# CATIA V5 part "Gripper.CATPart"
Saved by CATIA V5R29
Part number: Gripper
Bounding box of the stored display mesh (mm): x -95 to 95, y -290 to 38, z -94.974 to 283.5
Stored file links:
  C:\Users\Administrator\Desktop\프로젝트\Gripper\Gripper.CATPart
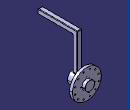
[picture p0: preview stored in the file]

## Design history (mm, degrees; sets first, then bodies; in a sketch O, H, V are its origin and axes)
Body1 (main body)
  Sketch1 on zx-plane, origin (0, 0, 0), H (-1, 0, 0), V (0, 0, 1)
    circle A1 centre (0, 0) radius 95
    radius A1 = 95
  Pad1: profile Sketch1, direction (0, 1, 0), length 18
  Sketch2 on end face of Pad1, origin (0, 18, 0), H (-1, 0, 0), V (0, 0, 1)
    circle A1 centre (0, 40) radius 2.459
    point P1 (0, 40)
    radius A1 = 2.459
    distance P1 H = 40
    coincidence: P1 V
  Pad2: profile Sketch2, direction (0, 1, 0), length 15
  CircPattern1: of Pad2, instances 5, angular step 90, axis from face of Pad1 from Sketch1.A1
  Sketch3 on end face of Pad1, origin (0, 18, 0), H (-1, 0, 0), V (0, 0, 1)
    circle A1 centre (56.5685, 56.5685) radius 5
    point P1 (56.5685, 56.5685)
    construction circle A2 centre (0, 0) radius 80
    construction line L1 (56.5685, 56.5685) -> (0, 0)
    radius A1 = 5
    radius A2 = 80
    angle L1 H = 45
    coincidence: P1 A2
  Pocket1: profile Sketch3, direction (0, -1, 0), through (limit type 6)
  CircPattern2: of Pocket1, instances 2, angular step 180, axis from face of Pad1 from Sketch1.A1
  Sketch4 on end face of Pad1, origin (0, 18, 0), H (-1, 0, 0), V (0, 0, 1)
    circle A1 centre (77.2741, 20.7055) radius 4.188
    construction line L1 (77.2741, 20.7055) -> (0, 0)
    construction line L2 (56.5685, 56.5685) -> (0, 0)
    point P2 (56.5685, 56.5685)
    reference projected point E1 (56.5685, 56.5685) from axis of face of Pocket1 from Sketch3.A1
    radius A1 = 4.188
    angle L2 L1 = 30
    length L1 = 80
    coincidence: P2 E1
  Pocket2: profile Sketch4, direction (0, -1, 0), through (limit type 6)
  CircPattern3: of Pocket2, instances 5, angular step 30, axis from face of Pad1 from Sketch1.A1
  Sketch5 on end face of Pad1, origin (0, 18, 0), H (-1, 0, 0), V (0, 0, 1)
    circle A1 centre (20.7055, 77.2741) radius 4.188
    construction line L1 (20.7055, 77.2741) -> (0, 0)
    construction line L2 (56.5685, 56.5685) -> (0, 0)
    point P2 (56.5685, 56.5685)
    reference projected point E3 (56.5685, 56.5685) from axis of face of Pocket1 from Sketch3.A1
    radius A1 = 4.188
    angle L2 L1 = 30
    length L1 = 80
    coincidence: P2 E3
  Pocket3: profile Sketch5, direction (0, -1, 0), through (limit type 6)
  CircPattern4: of Pocket3, instances 5, angular step 30, axis from face of Pad1 from Sketch1.A1
  Sketch6 on end face of Pad1, origin (0, 18, 0), H (-1, 0, 0), V (0, 0, 1)
    circle A1 centre (0, 0) radius 31.5
    radius A1 = 31.5
  Pad3: profile Sketch6, direction (0, 1, 0), length 20
  Fillet1: radius 1, on end face of Pad3
  Plane1: type Offset, RefPlane zx-plane, Offset 20, reversed
  Sketch7 on yz-plane, origin (0, 0, 0), H (0, 1, 0), V (0, 0, 1)
    line L1 (0, 60) -> (-20, 40)
  Sketch8 on Plane1, origin (0, -20, 0), H (-1, 0, 0), V (0, 0, 1)
    circle A1 centre (0, 0) radius 40
    radius A1 = 40
  Sketch9 on zx-plane, origin (0, 0, 0), H (-1, 0, 0), V (0, 0, 1)
    circle A1 centre (0, 0) radius 60
    radius A1 = 60
  Loft1: solid, Sections (Sketch8; Sketch9), Guides Sketch7
  Sketch10 on face of Loft1, origin (0, -20, 0), H (1, 0, 0), V (0, 0, 1)
    circle A1 centre (0, 0) radius 40
    reference projected circle E1 centre (0, 0) radius 40 from edge [face of Loft1 | face of Loft1]
    coincidence: A1 E1
  Pad4: profile Sketch10, direction (0, -1, 0), length 50
  Sketch11 on xy-plane, origin (0, 0, 0), H (1, 0, 0), V (0, 1, 0)
    point P1 (0, -45)
    line L1 (15, -30) -> (15, -60)
    line L2 (15, -60) -> (-15, -60)
    line L3 (-15, -60) -> (-15, -30)
    line L4 (-15, -30) -> (15, -30)
    reference intersected line E1 through (0, -20) direction (-1, 0) from Plane1
    distance L4 L2 = 30
    distance L1 L3 = 30
    distance L4 E1 = 10
    coincidence: P1 V
    vertical: L1 V, L3 V
    horizontal: L2 H, L4 H
    equidistance: L1 L3 P1, L2 L4 P1
  Pad5: profile Sketch11, direction (0, 0, 1), length 283.5
  Sketch12 on face of Pad5 from Sketch11.L2, origin (0, -60, 0), H (1, 0, 0), V (0, 0, 1)
    line L1 (-15, 283.5) -> (15, 283.5)
    line L2 (15, 283.5) -> (15, 253.5)
    line L3 (15, 253.5) -> (-15, 253.5)
    line L4 (-15, 253.5) -> (-15, 283.5)
    reference projected line E1 (15, 0) -> (15, 283.5) from edge [face of Pad5 from Sketch11.L1 | face of Pad5 from Sketch11.L2]
    reference projected line E2 (-15, 283.5) -> (15, 283.5) from edge [face of Pad5 from Sketch11.L2 | end face of Pad5]
    reference projected line E3 (-15, 0) -> (-15, 283.5) from edge [face of Pad5 from Sketch11.L2 | face of Pad5 from Sketch11.L3]
    distance L3 L1 = 30
    horizontal: L1 H, L3 H
    vertical: L2 V, L4 V
    coincidence: L2 E1, L1 E2, L4 E3
  Pad6: profile Sketch12, direction (0, -1, 0), length 230
  Fillet2: radius 3, on face of Pad5 from Sketch11.L2; face of Pad6 from Sketch12.L3; face of Pad6 (x3); face of Pad5 from Sketch11.L4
